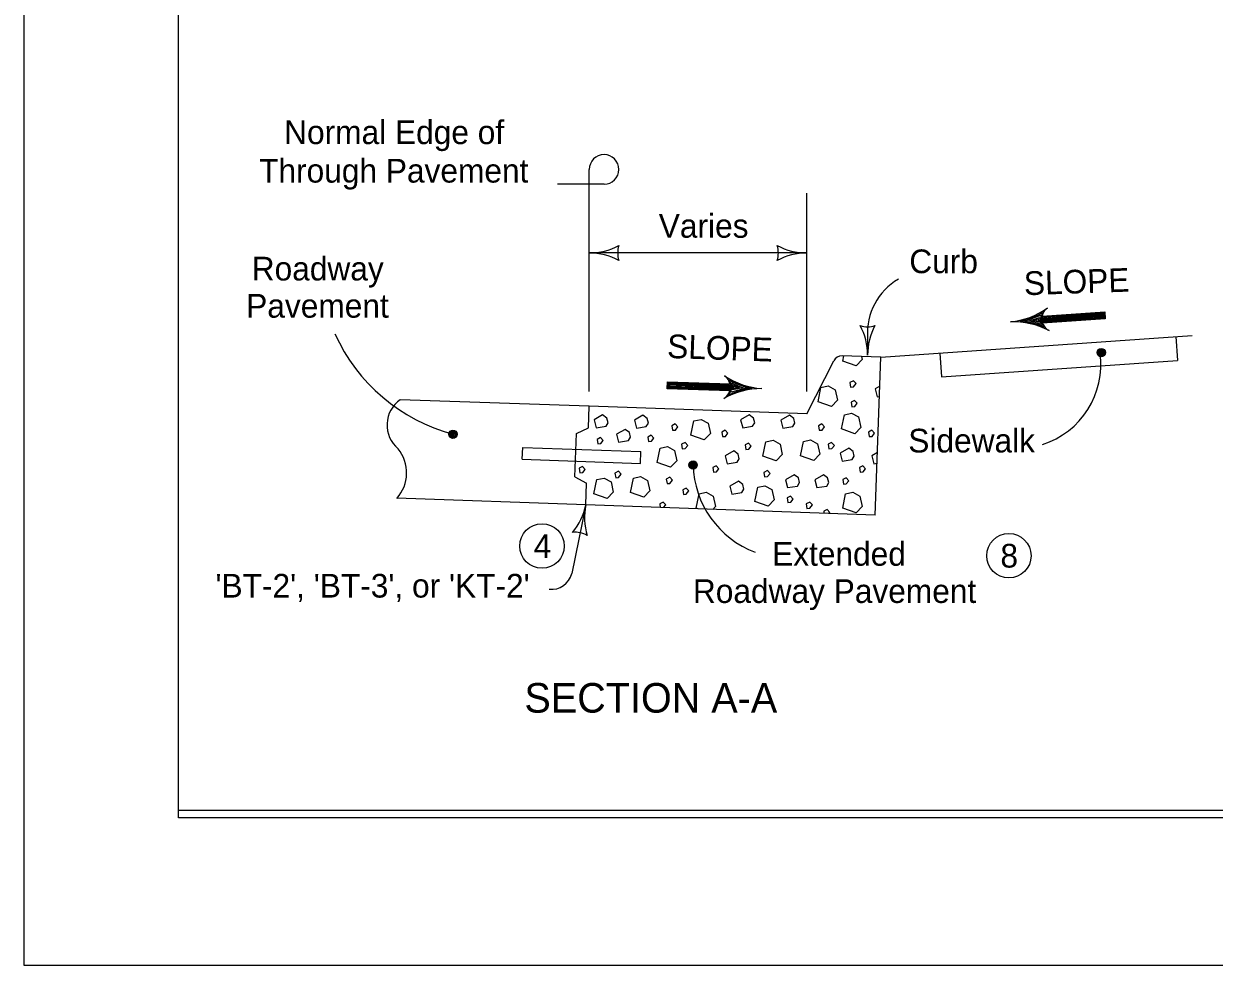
# Model space of a CAD drawing. Extents: x 10028 to 81668, y 6395 to 11634.
# Drawn here: x 10028 to 10833, y 7825 to 8460 of the extents above; entities that cross this region are included whole.
import ezdxf

# ---------------------------------------------------------------- set-up
doc = ezdxf.new("R2010")
doc.units = 0
for name, color, linetype in [('Default', 7, 'Continuous'), ('dsnCellElements', 7, 'Continuous'), ('dsnstdblockInterim', 7, 'Continuous'), ('dsnStdDimension', 7, 'Continuous'), ('ShtPlotIdentification', 7, 'Continuous')]:
    doc.layers.add(name, color=color, linetype=linetype)

msp = doc.modelspace()

# ---------------------------------------------------------------- linework, layer by layer
at = {"layer": 'Default'}
msp.add_lwpolyline([(10132.52, 9944.02), (13267.53, 9944.02), (13267.53, 7924.02), (10132.52, 7924.02)], close=True, dxfattribs=at)
msp.add_lwpolyline([(10132.52, 9944.02), (13267.53, 9944.02), (13267.53, 7924.02), (10132.52, 7924.02)], close=True, dxfattribs=at)
at = {"layer": 'dsnCellElements'}
msp.add_line((10598.29, 8248.87), (10598.29, 8236.61), dxfattribs=at)
for points in [[(10581.46, 8232.52), (10582.2, 8236.09)], [(10590.49, 8229.31), (10581.46, 8232.52)], [(10594.61, 8233.59), (10590.49, 8229.31)], [(10594.16, 8235.67), (10594.61, 8233.59)], [(10606.53, 8215.72), (10603.33, 8213.87)], [(10603.33, 8213.87), (10604.71, 8208.52)], [(10604.71, 8208.52), (10606.29, 8208.77)], [(10604.96, 8170.79), (10601.19, 8168.61)], [(10601.19, 8168.61), (10602.57, 8163.26)], [(10602.57, 8163.26), (10604.71, 8163.6)], [(10482.38, 8133.29), (10484.37, 8142.92)], [(10484.37, 8142.92), (10489.26, 8143.99)], [(10489.26, 8143.99), (10494, 8141.39)], [(10460.06, 8137.42), (10457.76, 8136.19)], [(10457.76, 8136.19), (10458.14, 8133.69)], [(10461.89, 8135.43), (10460.06, 8137.42)], [(10460.46, 8133.61), (10461.89, 8135.43)], [(10495.53, 8134.36), (10493.69, 8132.45)], [(10494, 8141.39), (10495.53, 8134.36)], [(10483.77, 8132.8), (10482.38, 8133.29)], [(10570.91, 8132.37), (10568.62, 8131.15)], [(10568.62, 8131.15), (10568.82, 8129.83)], [(10572.75, 8130.38), (10570.91, 8132.37)], [(10572.22, 8129.71), (10572.75, 8130.38)]]:
    msp.add_lwpolyline(points, dxfattribs=at)
for points in [[(10566.79, 8214.78), (10571.68, 8215.85), (10576.42, 8213.26), (10577.95, 8206.22), (10573.82, 8201.94), (10564.8, 8205.15)], [(10586.36, 8218.15), (10586.82, 8215.09), (10588.8, 8215.24), (10590.49, 8217.39), (10588.65, 8219.37)], [(10587.12, 8204.85), (10587.58, 8201.79), (10589.57, 8201.94), (10591.25, 8204.08), (10589.41, 8206.07)], [(10413.42, 8192.92), (10414.8, 8187.57), (10421.53, 8188.64), (10422.9, 8190.93), (10422.14, 8194.14), (10419.23, 8196.28)], [(10440.64, 8192.61), (10442.02, 8187.26), (10448.74, 8188.33), (10450.12, 8190.63), (10449.36, 8193.84), (10446.45, 8195.98)], [(10466.02, 8188.94), (10466.48, 8185.89), (10468.47, 8186.04), (10470.15, 8188.18), (10468.31, 8190.17)], [(10480.85, 8192.16), (10485.75, 8193.23), (10490.49, 8190.63), (10492.02, 8183.59), (10487.89, 8179.31), (10478.87, 8182.52)], [(10512.5, 8192.92), (10513.88, 8187.57), (10520.61, 8188.64), (10521.98, 8190.93), (10521.22, 8194.14), (10518.31, 8196.28)], [(10539.72, 8192.61), (10541.1, 8187.26), (10547.83, 8188.33), (10549.2, 8190.63), (10548.44, 8193.84), (10545.53, 8195.98)], [(10565.1, 8188.94), (10565.56, 8185.89), (10567.55, 8186.04), (10569.23, 8188.18), (10567.4, 8190.17)], [(10582.6, 8196.42), (10587.49, 8197.49), (10592.23, 8194.89), (10593.76, 8187.85), (10589.63, 8183.57), (10580.61, 8186.78)], [(10428.55, 8183.14), (10429.92, 8177.79), (10436.65, 8178.86), (10438.03, 8181.15), (10437.26, 8184.36), (10434.36, 8186.5)], [(10449.73, 8181.33), (10450.19, 8178.27), (10452.18, 8178.43), (10453.86, 8180.57), (10452.03, 8182.55)], [(10499.81, 8184.66), (10500.27, 8181.61), (10502.26, 8181.76), (10503.94, 8183.9), (10502.11, 8185.89)], [(10598.9, 8184.66), (10599.35, 8181.61), (10601.34, 8181.76), (10603.02, 8183.9), (10601.19, 8185.89)], [(10415.47, 8179.74), (10415.93, 8176.68), (10417.92, 8176.83), (10419.6, 8178.97), (10417.76, 8180.96)], [(10458.11, 8173.81), (10463.01, 8174.88), (10467.75, 8172.28), (10469.28, 8165.25), (10465.15, 8160.97), (10456.13, 8164.18)], [(10472.6, 8176.41), (10473.05, 8173.35), (10475.04, 8173.5), (10476.72, 8175.64), (10474.89, 8177.63)], [(10515.56, 8175.95), (10516.02, 8172.89), (10518.01, 8173.04), (10519.69, 8175.18), (10517.86, 8177.17)], [(10529.48, 8178.09), (10534.37, 8179.16), (10539.11, 8176.56), (10540.64, 8169.53), (10536.51, 8165.24), (10527.49, 8168.46)], [(10554.9, 8178.24), (10559.79, 8179.31), (10564.53, 8176.71), (10566.06, 8169.68), (10561.93, 8165.4), (10552.91, 8168.61)], [(10571.68, 8176.41), (10572.14, 8173.35), (10574.12, 8173.5), (10575.81, 8175.64), (10573.97, 8177.63)], [(10502.11, 8168.61), (10503.48, 8163.26), (10510.21, 8164.33), (10511.59, 8166.62), (10510.82, 8169.83), (10507.92, 8171.97)], [(10579.73, 8170.43), (10581.1, 8165.08), (10587.83, 8166.15), (10589.21, 8168.44), (10588.44, 8171.65), (10585.54, 8173.79)], [(10403.36, 8160.18), (10403.81, 8157.13), (10405.8, 8157.28), (10407.48, 8159.42), (10405.65, 8161.41)], [(10427.57, 8156.91), (10428.03, 8153.86), (10430.02, 8154.01), (10431.7, 8156.15), (10429.87, 8158.14)], [(10493.7, 8160.66), (10494.16, 8157.6), (10496.14, 8157.75), (10497.83, 8159.89), (10495.99, 8161.88)], [(10528.25, 8157.45), (10528.71, 8154.39), (10530.7, 8154.54), (10532.38, 8156.68), (10530.55, 8158.67)], [(10592.78, 8160.66), (10593.24, 8157.6), (10595.23, 8157.75), (10596.91, 8159.89), (10595.07, 8161.88)], [(10415.25, 8152.55), (10420.14, 8153.62), (10424.88, 8151.02), (10426.41, 8143.98), (10422.28, 8139.7), (10413.26, 8142.91)], [(10439.99, 8153.58), (10444.88, 8154.65), (10449.62, 8152.05), (10451.15, 8145.02), (10447.02, 8140.74), (10438, 8143.95)], [(10462.26, 8152.94), (10462.72, 8149.88), (10464.71, 8150.03), (10466.39, 8152.17), (10464.56, 8154.16)], [(10505.19, 8148.03), (10506.57, 8142.68), (10513.29, 8143.75), (10514.67, 8146.04), (10513.91, 8149.25), (10511, 8151.39)], [(10542.81, 8152.48), (10544.18, 8147.13), (10550.91, 8148.2), (10552.29, 8150.49), (10551.52, 8153.7), (10548.62, 8155.84)], [(10562.58, 8152.49), (10563.96, 8147.14), (10570.68, 8148.21), (10572.06, 8150.5), (10571.3, 8153.71), (10568.39, 8155.85)], [(10581.46, 8152.55), (10581.92, 8149.5), (10583.91, 8149.65), (10585.59, 8151.79), (10583.76, 8153.78)], [(10473.32, 8145.63), (10473.78, 8142.57), (10475.77, 8142.72), (10477.45, 8144.86), (10475.62, 8146.85)], [(10524.01, 8147.34), (10528.9, 8148.41), (10533.64, 8145.81), (10535.17, 8138.78), (10531.04, 8134.5), (10522.02, 8137.71)], [(10583.45, 8142.92), (10588.35, 8143.99), (10593.09, 8141.39), (10594.61, 8134.36), (10590.49, 8130.08), (10581.46, 8133.29)], [(10543.9, 8140.19), (10544.36, 8137.13), (10546.34, 8137.28), (10548.03, 8139.42), (10546.19, 8141.41)], [(10556.85, 8136.19), (10557.3, 8133.13), (10559.29, 8133.29), (10560.97, 8135.43), (10559.14, 8137.42)]]:
    msp.add_lwpolyline(points, close=True, dxfattribs=at)
at = {"layer": 'dsnstdblockInterim'}
for points in [[(10132.53, 9944.02), (13267.52, 9944.02), (13267.52, 7924.02), (10132.53, 7924.02)], [(10132.52, 9939.02), (13267.52, 9939.02), (13267.52, 7929.02), (10132.52, 7929.02)]]:
    msp.add_lwpolyline(points, close=True, dxfattribs=at)
at = {"layer": 'dsnStdDimension'}
msp.add_lwpolyline([(10028.02, 7824.52), (13372.02, 7824.52), (13372.02, 10408.52), (10028.02, 10408.52)], close=True, dxfattribs=at)
at = {"layer": 'ShtPlotIdentification'}
for p, q in [((10410.17, 8346.08), (10410.17, 8362.08)), ((10404.17, 8352.08), (10388.77, 8352.08)), ((10420.17, 8352.08), (10404.17, 8352.08)), ((10410.17, 8212.07), (10410.17, 8346.08)), ((10557.21, 8212.07), (10557.21, 8346.08)), ((10557.21, 8305.64), (10410.17, 8305.64)), ((10716.29, 8263.15), (10716.29, 8263.15)), ((10716.34, 8260.58), (10758.67, 8263.54)), ((10716.59, 8258.19), (10716.59, 8258.19)), ((10607.21, 8235.21), (10817.57, 8249.92)), ((10806.63, 8249.16), (10807.75, 8233.11)), ((10557.21, 8196.93), (10575.48, 8232.85)), ((10607.21, 8235.21), (10581.04, 8236.13)), ((10603.49, 8128.61), (10607.21, 8235.21)), ((10647.02, 8238), (10648.14, 8221.95)), ((10648.14, 8221.95), (10807.75, 8233.11)), ((10505.35, 8214.8), (10462.94, 8216.28)), ((10505.35, 8217.2), (10505.35, 8217.2)), ((10410.17, 8202.07), (10282.43, 8206.53)), ((10505.13, 8212.25), (10505.13, 8212.25)), ((10409.66, 8187.42), (10410.17, 8202.07)), ((10557.21, 8196.93), (10410.17, 8202.07)), ((10400.5, 8154.38), (10401.52, 8183.7)), ((10401.52, 8183.7), (10409.66, 8187.42)), ((10364.89, 8166.3), (10365.17, 8174.29)), ((10365.17, 8174.29), (10445.12, 8171.5)), ((10364.89, 8166.3), (10444.84, 8163.51)), ((10444.84, 8163.51), (10445.12, 8171.5)), ((10400.5, 8154.38), (10408.36, 8150.11)), ((10407.84, 8135.44), (10408.36, 8150.11)), ((10407.84, 8135.44), (10280.1, 8139.91)), ((10407.84, 8135.44), (10398.3, 8089.19)), ((10603.49, 8128.61), (10407.84, 8135.44))]:
    msp.add_line(p, q, dxfattribs=at)
for points in [[(10717.18, 8266.18), (10715.58, 8263.2), (10715.66, 8259.01), (10717.45, 8255.46), (10711.03, 8257.62), (10703.58, 8259.22), (10701.48, 8259.56), (10706.7, 8260.98), (10714.18, 8264.16), (10716.37, 8265.54), (10716.15, 8256.6), (10704.61, 8259.62), (10715.38, 8263.72), (10715.39, 8257.55), (10707.47, 8259.87), (10714.43, 8262.11), (10715, 8258.59), (10709.97, 8259.83), (10713.65, 8261.15), (10713.98, 8259.47), (10712.14, 8259.88)], [(10716.25, 8262.98), (10758.51, 8265.94), (10758.84, 8261.15), (10716.59, 8258.19), (10716.44, 8262.3), (10758, 8265.37), (10758.16, 8261.55), (10717.47, 8258.87), (10717.17, 8261.72), (10757.46, 8264.69), (10757.53, 8262.15), (10717.97, 8259.38), (10717.74, 8261.17), (10757.02, 8264.13), (10757.07, 8262.7), (10718.45, 8260.05)], [(10755.98, 8235.79), (10756.93, 8236.22), (10758.4, 8236.67), (10758.68, 8238.17), (10758.48, 8239.48), (10757.54, 8240.69), (10756.14, 8240.56), (10754.67, 8240.35), (10753.96, 8239.18), (10753.83, 8237.94), (10754.7, 8236.32), (10755.78, 8236.19), (10757.25, 8236.56), (10758.46, 8237.5), (10758.41, 8238.9), (10757.47, 8240.02), (10756.15, 8240.15), (10754.68, 8239.86), (10754.46, 8239.03), (10754.16, 8238.03), (10754.85, 8236.82), (10755.92, 8236.85), (10757.15, 8237.05), (10758.04, 8237.73), (10757.59, 8238.96), (10756.66, 8239.67), (10755.43, 8239.72), (10755.12, 8239.05), (10754.73, 8238.3), (10755.33, 8237.33), (10756.24, 8237.11), (10757.05, 8237.54), (10757.11, 8238.45), (10756.68, 8239.09), (10755.85, 8239.32), (10755.45, 8238.98), (10755.21, 8238.48), (10755.65, 8237.75), (10756.23, 8237.6), (10756.79, 8237.95), (10756.7, 8238.44), (10756.28, 8238.75), (10755.7, 8238.74), (10755.71, 8238.33), (10756.21, 8238.09)], [(10505.19, 8212.41), (10462.85, 8213.89), (10463.02, 8218.68), (10505.35, 8217.2), (10505.07, 8213.1), (10463.42, 8214.4), (10463.66, 8218.21), (10504.4, 8216.63), (10504.41, 8213.76), (10464.03, 8215.01), (10464.22, 8217.55), (10503.85, 8216.17), (10503.9, 8214.36), (10464.52, 8215.53), (10464.62, 8216.96), (10503.3, 8215.55)], [(10503.93, 8209.32), (10505.83, 8212.12), (10506.19, 8216.3), (10504.78, 8220.01), (10510.95, 8217.2), (10518.18, 8214.82), (10520.23, 8214.27), (10514.9, 8213.4), (10507.12, 8211.02), (10504.8, 8209.88), (10505.96, 8218.75), (10517.11, 8214.54), (10505.98, 8211.59), (10506.61, 8217.72), (10514.25, 8214.59), (10507.09, 8213.09), (10506.89, 8216.65), (10511.77, 8214.89), (10507.97, 8213.96), (10507.82, 8215.66), (10509.6, 8215.07)], [(10317.84, 8180.63), (10318.78, 8181.06), (10320.25, 8181.51), (10320.54, 8183), (10320.33, 8184.31), (10319.39, 8185.52), (10317.99, 8185.4), (10316.52, 8185.19), (10315.81, 8184.02), (10315.68, 8182.78), (10316.55, 8181.16), (10317.63, 8181.02), (10319.1, 8181.4), (10320.31, 8182.34), (10320.27, 8183.74), (10319.33, 8184.86), (10318.01, 8184.99), (10316.53, 8184.7), (10316.31, 8183.87), (10316.01, 8182.87), (10316.7, 8181.66), (10317.77, 8181.69), (10319, 8181.89), (10319.89, 8182.57), (10319.44, 8183.79), (10318.51, 8184.51), (10317.28, 8184.55), (10316.97, 8183.89), (10316.58, 8183.14), (10317.18, 8182.16), (10318.1, 8181.94), (10318.91, 8182.38), (10318.96, 8183.29), (10318.53, 8183.93), (10317.7, 8184.16), (10317.3, 8183.81), (10317.07, 8183.31), (10317.5, 8182.58), (10318.08, 8182.44), (10318.65, 8182.78), (10318.55, 8183.27), (10318.13, 8183.59), (10317.55, 8183.57), (10317.57, 8183.16), (10318.07, 8182.93)], [(10480.14, 8159.87), (10481.08, 8160.3), (10482.55, 8160.75), (10482.84, 8162.24), (10482.64, 8163.55), (10481.7, 8164.76), (10480.3, 8164.64), (10478.82, 8164.43), (10478.12, 8163.26), (10477.99, 8162.02), (10478.86, 8160.4), (10479.93, 8160.26), (10481.4, 8160.64), (10482.61, 8161.58), (10482.57, 8162.98), (10481.63, 8164.1), (10480.31, 8164.23), (10478.84, 8163.94), (10478.61, 8163.11), (10478.31, 8162.11), (10479.01, 8160.9), (10480.08, 8160.93), (10481.31, 8161.13), (10482.19, 8161.81), (10481.74, 8163.03), (10480.82, 8163.75), (10479.58, 8163.79), (10479.27, 8163.13), (10478.88, 8162.38), (10479.49, 8161.4), (10480.4, 8161.18), (10481.21, 8161.62), (10481.27, 8162.53), (10480.84, 8163.17), (10480.01, 8163.4), (10479.6, 8163.05), (10479.37, 8162.55), (10479.8, 8161.82), (10480.38, 8161.68), (10480.95, 8162.02), (10480.86, 8162.51), (10480.43, 8162.83), (10479.86, 8162.81), (10479.87, 8162.4), (10480.37, 8162.17)]]:
    msp.add_lwpolyline(points, dxfattribs=at)
for centre, radius in [((10756.2, 8238.36), 2.8), ((10318.05, 8183.2), 2.8), ((10480.36, 8162.44), 2.8), ((10378.25, 8107.69), 15), ((10693.78, 8101.13), 15)]:
    msp.add_circle(centre, radius, dxfattribs=at)
for centre, radius, start, end in [((10420.17, 8362.08), 10, 270, 180), ((10410.17, 8348.14), 42.5, 270, 298.07249), ((10410.17, 8348.14), 42.5, 270, 298.07249), ((10445.8, 8305.64), 16.42, 162.26665, 197.73335), ((10445.8, 8305.64), 16.42, 162.26665, 197.73335), ((10521.58, 8305.64), 16.42, 342.26665, 17.73335), ((10557.21, 8348.14), 42.5, 241.92751, 270), ((10521.58, 8305.64), 16.42, 342.26665, 17.73335), ((10557.21, 8348.14), 42.5, 241.92751, 270), ((10410.17, 8263.14), 42.5, 61.92751, 90), ((10410.17, 8263.14), 42.5, 61.92751, 90), ((10557.21, 8263.14), 42.5, 90, 118.07249), ((10557.21, 8263.14), 42.5, 90, 118.07249), ((10640.34, 8251.61), 42.14, 120.30159, 183.73986), ((10689.72, 8310.41), 51.58, 275.6841, 305.71413), ((10725.1, 8261.2), 9.03, 125.71455, 242.28519), ((10598.29, 8272.24), 16.42, 252.26665, 287.73335), ((10555.79, 8236.61), 42.5, 360, 28.07249), ((10640.79, 8236.61), 42.5, 151.92751, 180), ((10696.91, 8207.54), 51.58, 62.28561, 92.31564), ((10349.97, 8301.51), 122.54, 204.30911, 254.90087), ((10580.83, 8230.13), 6, 88.0031, 153.04351), ((10698.87, 8230.57), 57.14, 287.91506, 7.34773), ((10496.57, 8215.11), 9.03, 299.71442, 56.28506), ((10530.21, 8265.53), 51.58, 236.28548, 266.31551), ((10294.33, 8189.42), 20.85, 124.83209, 230.03769), ((10526.61, 8162.47), 51.58, 89.68397, 119.714), ((10261.05, 8157.16), 25.71, 317.82833, 39.2857), ((10545.28, 8164.22), 64.95, 181.57038, 249.26371), ((10366.22, 8144.03), 42.5, 320.27547, 348.34796), ((10449.47, 8126.86), 42.5, 168.34796, 196.42045), ((10400.65, 8100.54), 16.42, 60.61461, 96.08131), ((10384.86, 8092.25), 13.79, 262.53394, 347.15522)]:
    msp.add_arc(centre, radius, start, end, dxfattribs=at)

# ---------------------------------------------------------------- texts
at = {"layer": 'dsnCellElements'}
for s, height, p in [('Normal Edge of', 16, (10203.99, 8379.21)), ('Through Pavement', 16, (10187.06, 8353.21)), ('Varies', 16, (10457.15, 8315.95)), ('Roadway', 16, (10182.07, 8287.08)), ('Curb', 16, (10626.48, 8292.01)), ('Pavement', 16, (10178.32, 8261.93)), ('Sidewalk', 16, (10625.79, 8170.88)), ('4', 16, (10372.58, 8099.69)), ('Extended ', 16, (10533.75, 8094.36)), ("'BT-2', 'BT-3', or 'KT-2'", 16, (10157.56, 8072.86)), ('Roadway Pavement', 16, (10480.23, 8069.22)), ('SECTION A-A', 20, (10366.35, 7995.12))]:
    msp.add_text(s, height=height, dxfattribs=at).set_placement(p)
for rotation, p in [(1.99987, (10704.19, 8277.08)), (358, (10462.62, 8234.75))]:
    msp.add_text('SLOPE', height=16, rotation=rotation, dxfattribs=at).set_placement(p)
at = {"layer": 'ShtPlotIdentification'}
msp.add_text('8', height=16, dxfattribs=at).set_placement((10688.06, 8093.13))

doc.saveas('drawing.dxf')
